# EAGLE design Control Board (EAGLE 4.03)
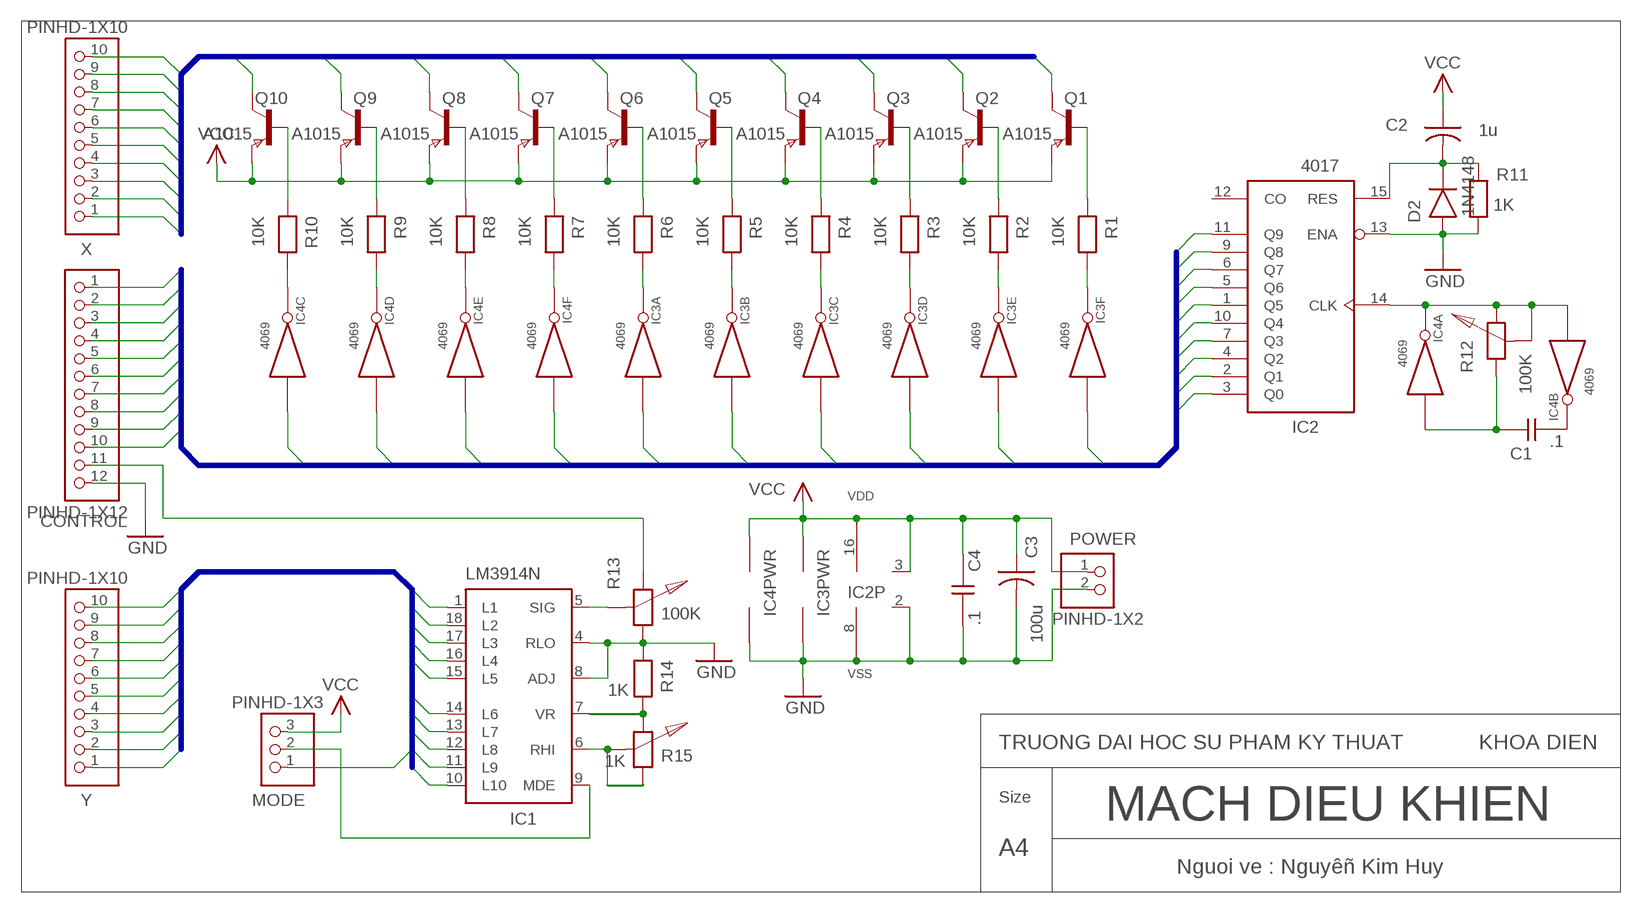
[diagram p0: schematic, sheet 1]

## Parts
C1  .1  CAPNP-5  [C-5]
C2  1u  CAP-5  [C-5]
C3  100u  CAP-5  [C-5]
C4  .1  CAPNP-5  [C-5]
CONTROL  PINHD-1X12  [1X12]
D2  1N4148  DIODE-10  [D-10]
IC1  LM3914N  [DIL-18]
IC2  4017  [DIL-16]
IC3  4069  [DIL-14]
IC4  4069  [DIL-14]
MODE  PINHD-1X3  [1X03]
POWER  PINHD-1X2  [1X02]
Q1  A1015  [TO-92B]
Q2  A1015  [TO-92B]
Q3  A1015  [TO-92B]
Q4  A1015  [TO-92B]
Q5  A1015  [TO-92B]
Q6  A1015  [TO-92B]
Q7  A1015  [TO-92B]
Q8  A1015  [TO-92B]
Q9  A1015  [TO-92B]
Q10  A1015  [TO-92B]
R1  10K  RESEU-10  [R-10]
R2  10K  RESEU-10  [R-10]
R3  10K  RESEU-10  [R-10]
R4  10K  RESEU-10  [R-10]
R5  10K  RESEU-10  [R-10]
R6  10K  RESEU-10  [R-10]
R7  10K  RESEU-10  [R-10]
R8  10K  RESEU-10  [R-10]
R9  10K  RESEU-10  [R-10]
R10  10K  RESEU-10  [R-10]
R11  1K  RESEU-10  [R-10]
R12  100K  POT-S  [PT-10S]
R13  100K  POT-S  [PT-10S]
R14  1K  RESEU-10  [R-10]
R15  1K  POT-S  [PT-10S]
X  PINHD-1X10  [1X10]
Y  PINHD-1X10  [1X10]

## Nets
GND: C3.2 C4.1 CONTROL.12 D2.1(A) IC1.2(V-) IC1.4(RLO) IC1.8(ADJ) IC2.8(VSS) IC2.13(ENA) IC3.7(PWR:GND) IC4.7(PWR:GND) POWER.2 R11.1 R13.1 R14.1
INPUT: CONTROL.11 R13.2
N$1: IC3.12 R1.2
N$2: IC3.10 R2.2
N$3: IC3.8 R3.2
N$4: IC2.14(CLK) IC4.2 IC4.3 R12.2 R12.3
N$5: Q1.1(B) R1.1
N$6: Q10.1(B) R10.1
N$7: Q2.1(B) R2.1
N$8: Q9.1(B) R9.1
N$9: IC1.9(MDE) MODE.2
N$10: Q8.1(B) R8.1
N$11: IC4.6 R10.2
N$12: IC4.8 R9.2
N$13: IC4.10 R8.2
N$14: Q7.1(B) R7.1
N$15: Q3.1(B) R3.1
N$16: C2.2 D2.2(K) IC2.15(RES) R11.2
N$17: IC1.5(SIG) R13.3
N$18: C1.1 IC4.4
N$19: IC3.4 R5.2
N$20: IC4.12 R7.2
N$21: IC3.2 R6.2
N$22: Q6.1(B) R6.1
N$23: C1.2 IC4.1 R12.1
N$24: IC1.7(VR) R14.2 R15.2
N$26: IC3.6 R4.2
N$27: Q5.1(B) R5.1
N$28: Q4.1(B) R4.1
N$30: IC1.6(RHI) R15.1 R15.3
SWEEP0: CONTROL.1 IC2.3(Q0) IC3.13
SWEEP1: CONTROL.2 IC2.2(Q1) IC3.11
SWEEP2: CONTROL.3 IC2.4(Q2) IC3.9
SWEEP3: CONTROL.4 IC2.7(Q3) IC3.5
SWEEP4: CONTROL.5 IC2.10(Q4) IC3.3
SWEEP5: CONTROL.6 IC2.1(Q5) IC3.1
SWEEP6: CONTROL.7 IC2.5(Q6) IC4.13
SWEEP7: CONTROL.8 IC2.6(Q7) IC4.11
SWEEP8: CONTROL.9 IC2.9(Q8) IC4.9
SWEEP9: CONTROL.10 IC2.11(Q9) IC4.5
VCC: C2.1 C3.1 C4.2 IC1.3(V+) IC2.16(VDD) IC3.14(PWR:VCC) IC4.14(PWR:VCC) MODE.3 POWER.1 Q1.3(E) Q2.3(E) Q3.3(E) Q4.3(E) Q5.3(E) Q6.3(E) Q7.3(E) Q8.3(E) Q9.3(E) Q10.3(E)
X0: Q1.2(C) X.1
X1: Q2.2(C) X.2
X2: Q3.2(C) X.3
X3: Q4.2(C) X.4
X4: Q5.2(C) X.5
X5: Q6.2(C) X.6
X6: Q7.2(C) X.7
X7: Q8.2(C) X.8
X8: Q9.2(C) X.9
X9: Q10.2(C) X.10
Y0: IC1.1(L1) Y.1
Y1: IC1.18(L2) Y.2
Y2: IC1.17(L3) Y.3
Y3: IC1.16(L4) Y.4
Y4: IC1.15(L5) Y.5
Y5: IC1.14(L6) Y.6
Y6: IC1.13(L7) Y.7
Y7: IC1.12(L8) Y.8
Y8: IC1.11(L9) MODE.1 Y.9
Y9: IC1.10(L10) Y.10
Unconnected: IC2.12(CO)

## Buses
SWEEP[0..9]
X[0..9]
Y[0..9]

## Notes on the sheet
- TRUONG DAI HOC SU PHAM KY THUAT | KHOA DIEN
- Size
- MACH DIEU KHIEN
- A4
- Nguoi ve : Nguyêñ Kim Huy

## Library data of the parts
C1 C4 = DISCRETE:CAPNP-5
C2 C3 = DISCRETE:CAP-5
CONTROL = PINHEAD:PINHD-1X12
D2 = DISCRETE:DIODE-10
IC1 = LINEAR:LM3914N
IC2 = 40XX:4017
IC3 IC4 = HUY:4069
MODE = PINHEAD:PINHD-1X3
POWER = PINHEAD:PINHD-1X2
Q1-Q10 = PNP:A1015
R1-R11 R14 = DISCRETE:RESEU-10
R12 R13 R15 = DISCRETE:POT-S
X Y = PINHEAD:PINHD-1X10

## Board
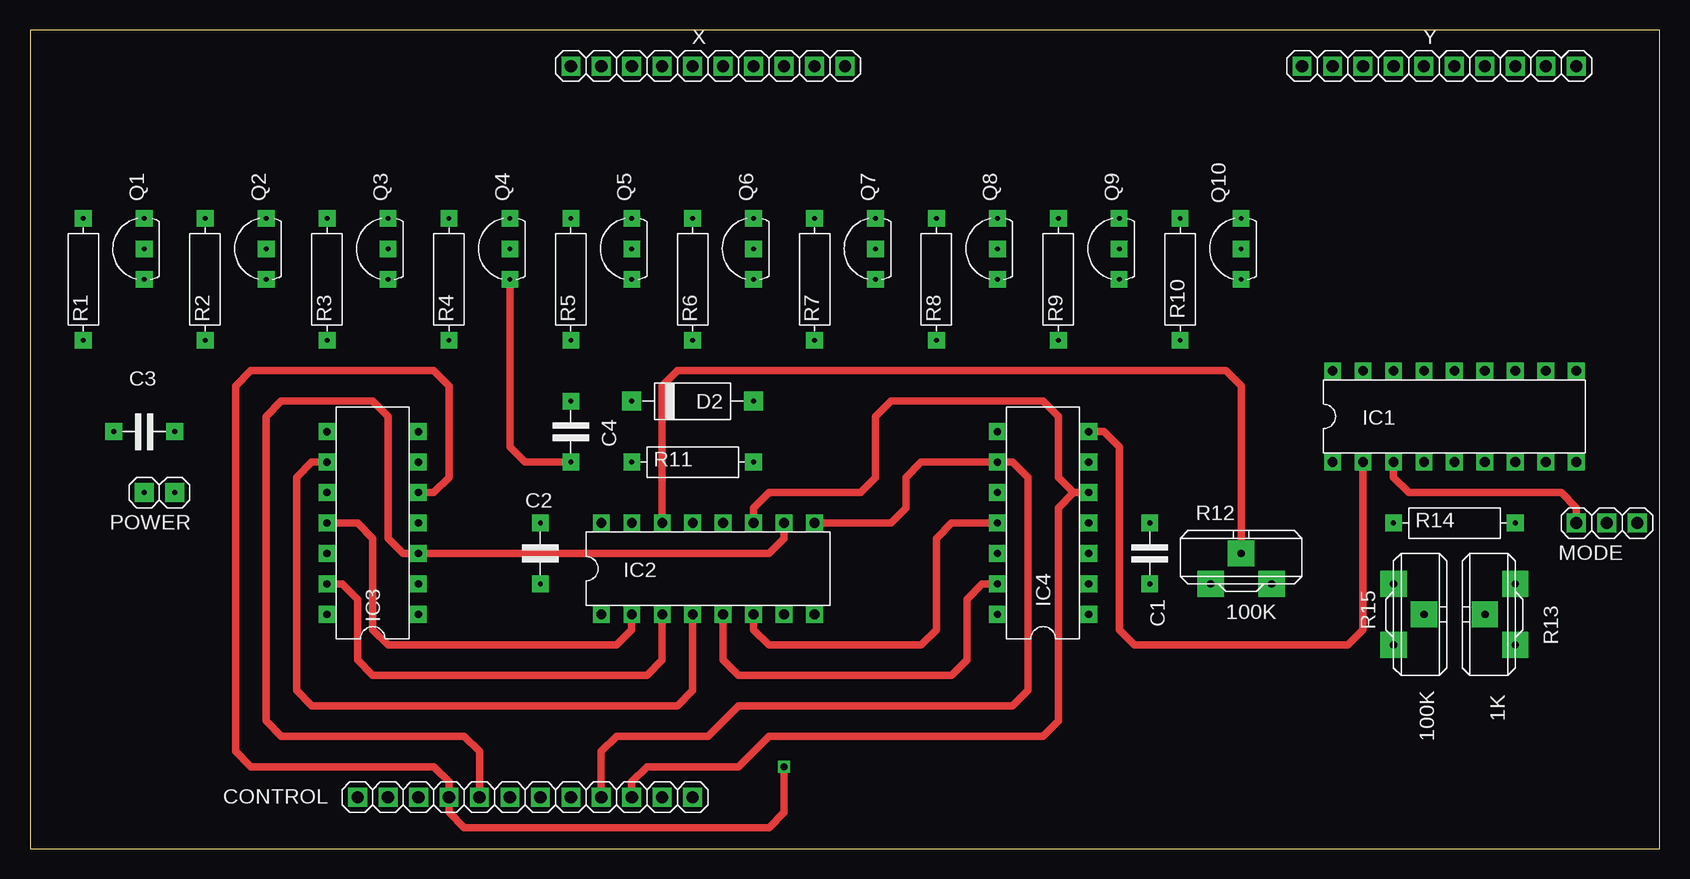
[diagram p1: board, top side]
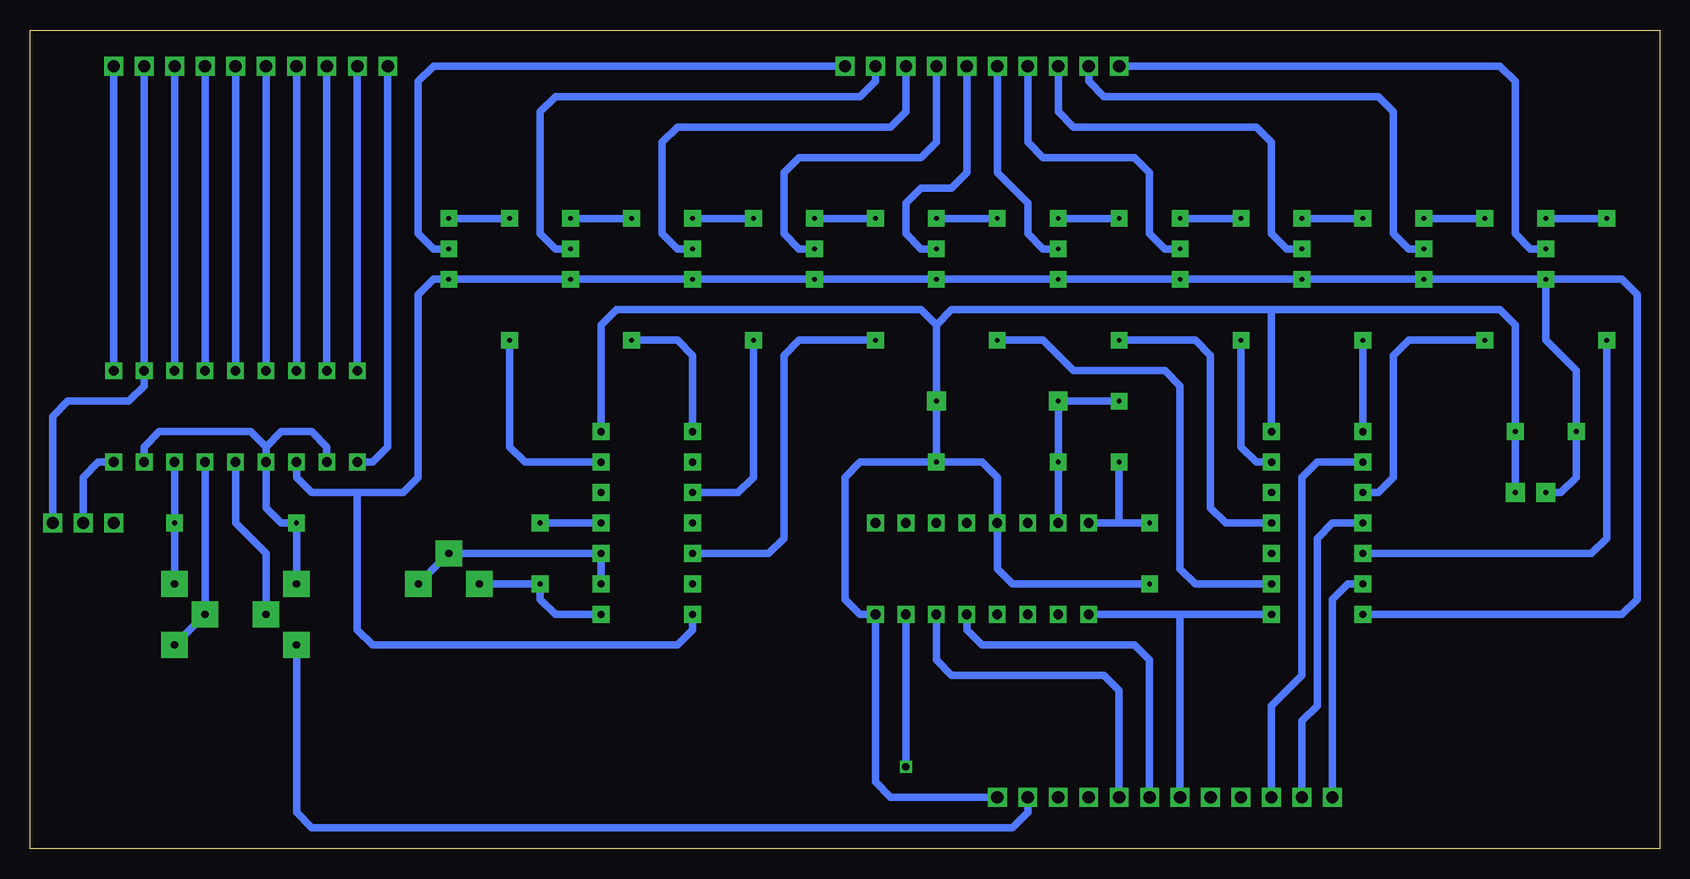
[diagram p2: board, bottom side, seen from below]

Size 135.87 x 68.25 mm. Coordinates in mm from the lower left corner, seen from the top.
Outline: 0,0 135.87,0 135.87,68.25 0,68.25 0,0
Copper layers used: Top, Bottom

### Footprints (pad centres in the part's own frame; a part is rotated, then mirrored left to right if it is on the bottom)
C-5 = drill 0.406 pad 1.397 square: 1 -2.54,0; 2 2.54,0
1X12 = drill 1.016 pad 1.575 square: 1 -13.97,0; 2 -11.43,0; 3 -8.89,0; 4 -6.35,0; 5 -3.81,0; 6 -1.27,0; 7 1.27,0; 8 3.81,0; 9 6.35,0; 10 8.89,0; 11 11.43,0; 12 13.97,0
D-10 = drill 0.406 pad 1.575 square: 1 -5.08,0; 2 5.08,0
DIL-18 = drill 0.813 pad 1.397 square: 1 -10.16,-3.81; 2 -7.62,-3.81; 3 -5.08,-3.81; 4 -2.54,-3.81; 5 0,-3.81; 6 2.54,-3.81; 7 5.08,-3.81; 8 7.62,-3.81; 9 10.16,-3.81; 10 10.16,3.81; 11 7.62,3.81; 12 5.08,3.81; 13 2.54,3.81; 14 0,3.81; 15 -2.54,3.81; 16 -5.08,3.81; 17 -7.62,3.81; 18 -10.16,3.81
DIL-16 = drill 0.813 pad 1.397 square: 1 -8.89,-3.81; 2 -6.35,-3.81; 3 -3.81,-3.81; 4 -1.27,-3.81; 5 1.27,-3.81; 6 3.81,-3.81; 7 6.35,-3.81; 8 8.89,-3.81; 9 8.89,3.81; 10 6.35,3.81; 11 3.81,3.81; 12 1.27,3.81; 13 -1.27,3.81; 14 -3.81,3.81; 15 -6.35,3.81; 16 -8.89,3.81
DIL-14 = drill 0.61 pad 1.397 square: 1 -7.62,-3.81; 2 -5.08,-3.81; 3 -2.54,-3.81; 4 0,-3.81; 5 2.54,-3.81; 6 5.08,-3.81; 7 7.62,-3.81; 8 7.62,3.81; 9 5.08,3.81; 10 2.54,3.81; 11 0,3.81; 12 -2.54,3.81; 13 -5.08,3.81; 14 -7.62,3.81
1X03 = drill 1.016 pad 1.575 square: 1 -2.54,0; 2 0,0; 3 2.54,0
1X02 = drill 0.406 pad 1.575 square: 1 -1.27,0; 2 1.27,0
TO-92B = drill 0.406 pad 1.397 square: 1 2.54,0; 2 0,0; 3 -2.54,0
R-10 = drill 0.406 pad 1.397 square: 1 -5.08,0; 2 5.08,0
PT-10S = drill 0.61 pad 2.184 square: 1 -2.54,-1.27; 2 2.54,-1.27; 3 0,1.27
1X10 = drill 1.016 pad 1.575 square: 1 -11.43,0; 2 -8.89,0; 3 -6.35,0; 4 -3.81,0; 5 -1.27,0; 6 1.27,0; 7 3.81,0; 8 6.35,0; 9 8.89,0; 10 11.43,0

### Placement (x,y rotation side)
C1  93.34,24.6 270 top
C2  45.08,34.76 90 top
C3  9.52,34.76 0 top
C4  42.54,24.6 90 top
CONTROL  41.27,4.28 0 top
D2  55.24,37.3 180 top
IC1  118.74,36.03 0 top
IC2  56.51,23.33 0 top
IC3  28.57,27.14 90 top
IC4  84.45,27.14 90 top
MODE  131.44,27.14 180 top
POWER  10.79,29.68 0 top
Q1  9.52,50 90 top
Q2  19.68,50 90 top
Q3  29.84,50 90 top
Q4  40,50 90 top
Q5  50.16,50 90 top
Q6  60.32,50 90 top
Q7  70.48,50 90 top
Q8  80.64,50 90 top
Q9  90.8,50 90 top
Q10  100.96,50 90 top
R1  4.44,47.46 270 top
R2  14.6,47.46 270 top
R3  24.76,47.46 270 top
R4  34.92,47.46 270 top
R5  45.08,47.46 270 top
R6  55.24,47.46 270 top
R7  65.4,47.46 270 top
R8  75.56,47.46 270 top
R9  85.72,47.46 270 top
R10  95.88,47.46 270 top
R11  55.24,32.22 180 top
R12  100.96,23.33 0 top
R13  114.93,19.52 270 top
R14  118.74,27.14 0 top
R15  122.55,19.52 90 top
X  56.51,65.24 0 top
Y  117.47,65.24 0 top

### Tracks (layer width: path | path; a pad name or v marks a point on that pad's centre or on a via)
GND
  Top 0.61: IC4.7 89.53,34.76 90.8,33.49 90.8,18.25 92.07,16.98 109.85,16.98 111.12,18.25 IC1.2
  Bottom 0.61: IC1.8 126.36,33.49 125.09,34.76 117.47,34.76 116.2,33.49 | 116.2,33.49 IC1.4 116.2,28.41 114.93,27.14 R14.1 R13.1 | IC1.2 111.12,33.49 112.39,34.76 114.93,34.76 116.2,33.49 | 32.38,44.92 IC3.7 | 32.38,44.92 59.05,44.92 60.32,43.65 | 32.38,44.92 13.33,44.92 12.06,43.65 C3.2 POWER.2 | R11.1 D2.1 60.32,43.65 | R11.1 56.51,32.22 55.24,30.95 IC2.13 55.24,23.33 53.97,22.06 C4.1 | 60.32,43.65 R11.1 | 60.32,43.65 61.59,44.92 86.99,44.92 88.26,43.65 IC4.7 | R11.1 66.67,32.22 67.94,30.95 67.94,20.79 66.67,19.52 IC2.8 65.4,5.55 64.13,4.28 CONTROL.12
INPUT
  Bottom 0.61: CONTROL.11 52.7,3.01 53.97,1.74 112.39,1.74 113.66,3.01 R13.2
N$1
  Bottom 0.61: R1.2 4.44,25.87 5.71,24.6 IC3.12
N$2
  Bottom 0.61: R2.2 20.95,42.38 22.22,41.11 22.22,30.95 23.49,29.68 IC3.10
N$3
  Bottom 0.61: IC3.8 R3.2
N$4
  Top 0.61: IC2.14 52.7,38.57 53.97,39.84 99.69,39.84 100.96,38.57 R12.3
  Bottom 0.61: R12.2 R12.3 IC4.3 IC4.2
N$5
  Bottom 0.61: R1.1 Q1.1
N$6
  Bottom 0.61: R10.1 Q10.1
N$7
  Bottom 0.61: R2.1 Q2.1
N$8
  Bottom 0.61: R9.1 Q9.1
N$9
  Bottom 0.61: MODE.2 131.44,30.95 130.17,32.22 IC1.9
N$10
  Bottom 0.61: R8.1 Q8.1
N$11
  Bottom 0.61: R10.2 95.88,33.49 94.61,32.22 IC4.6
N$12
  Bottom 0.61: R9.2 81.91,42.38 80.64,41.11 IC4.8
N$13
  Bottom 0.61: R8.2 75.56,30.95 76.83,29.68 IC4.10
N$14
  Bottom 0.61: R7.1 Q7.1
N$15
  Bottom 0.61: R3.1 Q3.1
N$16
  Bottom 0.61: C2.2 D2.2 R11.2 IC2.15
N$17
  Bottom 0.61: R13.3 116.2,24.6 118.74,27.14 IC1.5
N$18
  Bottom 0.61: IC4.4 C1.1
N$19
  Bottom 0.61: R5.2 38.73,42.38 37.46,41.11 37.46,28.41 36.19,27.14 IC3.4
N$20
  Bottom 0.61: R7.2 71.75,42.38 73.02,41.11 73.02,25.87 74.29,24.6 IC4.12
N$21
  Bottom 0.61: R6.2 51.43,42.38 48.89,39.84 41.27,39.84 40,38.57 40,23.33 38.73,22.06 IC3.2
N$22
  Bottom 0.61: R6.1 Q6.1
N$23
  Bottom 0.61: IC4.1 92.07,19.52 93.34,20.79 C1.2 R12.1
N$24
  Bottom 0.61: IC1.7 R14.2 R15.2
N$26
  Bottom 0.61: R4.2 34.92,33.49 33.65,32.22 IC3.6
N$27
  Bottom 0.61: R5.1 Q5.1
N$28
  Bottom 0.61: R4.1 Q4.1
N$30
  Bottom 0.61: R15.1 R15.3 IC1.6
SWEEP0
  Top 0.61: IC3.13 26.03,22.06 27.3,20.79 27.3,15.71 28.57,14.44 51.43,14.44 52.7,15.71 IC2.3
  Bottom 0.61: CONTROL.1 27.3,20.79 26.03,22.06 IC3.13
SWEEP1
  Top 0.61: IC3.11 27.3,27.14 28.57,25.87 28.57,18.25 29.84,16.98 48.89,16.98 50.16,18.25 IC2.2
  Bottom 0.61: CONTROL.2 29.84,10.63 28.57,11.9 28.57,25.87 27.3,27.14 IC3.11
SWEEP2
  Top 0.61: IC3.9 23.49,32.22 22.22,30.95 22.22,13.17 23.49,11.9 53.97,11.9 55.24,13.17 IC2.4
  Bottom 0.61: CONTROL.3 32.38,11.9 29.84,14.44 29.84,30.95 28.57,32.22 IC3.9
SWEEP3  (via drill 0.61 pad 1.02)
  Top 0.61: IC3.5 33.65,29.68 34.92,30.95 34.92,38.57 33.65,39.84 18.41,39.84 17.14,38.57 17.14,8.09 18.41,6.82 33.65,6.82 34.92,5.55 CONTROL.4 34.92,3.01 36.19,1.74 61.59,1.74 62.86,3.01 v62.86,6.82
  Bottom 0.61: v62.86,6.82 IC2.7
SWEEP4
  Top 0.61: IC2.10 62.86,25.87 61.59,24.6 IC3.3 31.11,24.6 29.84,25.87 29.84,36.03 28.57,37.3 20.95,37.3 19.68,36.03 19.68,10.63 20.95,9.36 36.19,9.36 37.46,8.09 CONTROL.5
SWEEP5
  Bottom 0.61: 40,19.52 IC3.1 | 40,19.52 IC2.1 | CONTROL.6 40,19.52
SWEEP6
  Top 0.61: IC2.5 57.78,15.71 59.05,14.44 76.83,14.44 78.1,15.71 78.1,20.79 79.37,22.06 IC4.13
  Bottom 0.61: CONTROL.7 42.54,15.71 43.81,16.98 56.51,16.98 57.78,18.25 IC2.5
SWEEP7
  Top 0.61: IC2.6 60.32,18.25 61.59,16.98 74.29,16.98 75.56,18.25 75.56,25.87 76.83,27.14 IC4.11
  Bottom 0.61: CONTROL.8 45.08,13.17 46.35,14.44 59.05,14.44 60.32,15.71 IC2.6
SWEEP8
  Top 0.61: IC2.9 71.75,27.14 73.02,28.41 73.02,30.95 74.29,32.22 IC4.9 81.91,32.22 83.18,30.95 83.18,13.17 81.91,11.9 59.05,11.9 56.51,9.36 48.89,9.36 47.62,8.09 CONTROL.9
SWEEP9
  Top 0.61: IC2.11 60.32,28.41 61.59,29.68 69.21,29.68 70.48,30.95 70.48,36.03 71.75,37.3 84.45,37.3 85.72,36.03 85.72,30.95 86.99,29.68 | 86.99,29.68 IC4.5 | 86.99,29.68 85.72,28.41 85.72,10.63 84.45,9.36 61.59,9.36 59.05,6.82 51.43,6.82 50.16,5.55 CONTROL.10
VCC
  Top 0.61: Q4.3 40,33.49 41.27,32.22 C2.1 | IC1.3 113.66,30.95 114.93,29.68 127.63,29.68 128.9,28.41 MODE.3
  Bottom 0.61: Q1.3 Q2.3 Q3.3 Q4.3 Q5.3 Q6.3 Q7.3 Q8.3 Q9.3 Q10.3 102.23,47.46 103.5,46.19 103.5,30.95 104.77,29.68 108.58,29.68 | IC3.14 3.17,19.52 1.9,20.79 1.9,46.19 3.17,47.46 Q1.3 | Q1.3 9.52,42.38 6.98,39.84 C3.1 6.98,30.95 8.25,29.68 POWER.1 | 108.58,29.68 112.39,29.68 113.66,30.95 IC1.3 | C2.1 45.08,27.14 | 45.08,27.14 IC2.16 | 45.08,27.14 C4.2 | IC4.14 80.64,18.25 81.91,16.98 107.31,16.98 108.58,18.25 108.58,29.68
X0
  Bottom 0.61: Q1.2 10.79,50 12.06,51.27 12.06,63.97 13.33,65.24 X.1
X1
  Bottom 0.61: Q2.2 20.95,50 22.22,51.27 22.22,61.43 23.49,62.7 46.35,62.7 47.62,63.97 X.2
X2
  Bottom 0.61: Q3.2 31.11,50 32.38,51.27 32.38,58.89 33.65,60.16 48.89,60.16 50.16,61.43 X.3
X3
  Bottom 0.61: Q4.2 41.27,50 42.54,51.27 42.54,56.35 43.81,57.62 51.43,57.62 52.7,58.89 X.4
X4
  Bottom 0.61: Q5.2 51.43,50 52.7,51.27 52.7,53.81 55.24,56.35 X.5
X5
  Bottom 0.61: Q6.2 61.59,50 62.86,51.27 62.86,53.81 61.59,55.08 59.05,55.08 57.78,56.35 X.6
X6
  Bottom 0.61: Q7.2 71.75,50 73.02,51.27 73.02,56.35 71.75,57.62 61.59,57.62 60.32,58.89 X.7
X7
  Bottom 0.61: Q8.2 81.91,50 83.18,51.27 83.18,58.89 81.91,60.16 64.13,60.16 62.86,61.43 X.8
X8
  Bottom 0.61: Q9.2 92.07,50 93.34,51.27 93.34,61.43 92.07,62.7 66.67,62.7 65.4,63.97 X.9
X9
  Bottom 0.61: Q10.2 102.23,50 103.5,51.27 103.5,63.97 102.23,65.24 X.10
Y0
  Bottom 0.61: Y.1 106.04,33.49 107.31,32.22 IC1.1
Y1
  Bottom 0.61: IC1.18 Y.2
Y2
  Bottom 0.61: IC1.17 Y.3
Y3
  Bottom 0.61: IC1.16 Y.4
Y4
  Bottom 0.61: IC1.15 Y.5
Y5
  Bottom 0.61: IC1.14 Y.6
Y6
  Bottom 0.61: IC1.13 Y.7
Y7
  Bottom 0.61: IC1.12 Y.8
Y8
  Bottom 0.61: Y.9 IC1.11 126.36,38.57 127.63,37.3 132.71,37.3 133.98,36.03 MODE.1
Y9
  Bottom 0.61: IC1.10 Y.10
